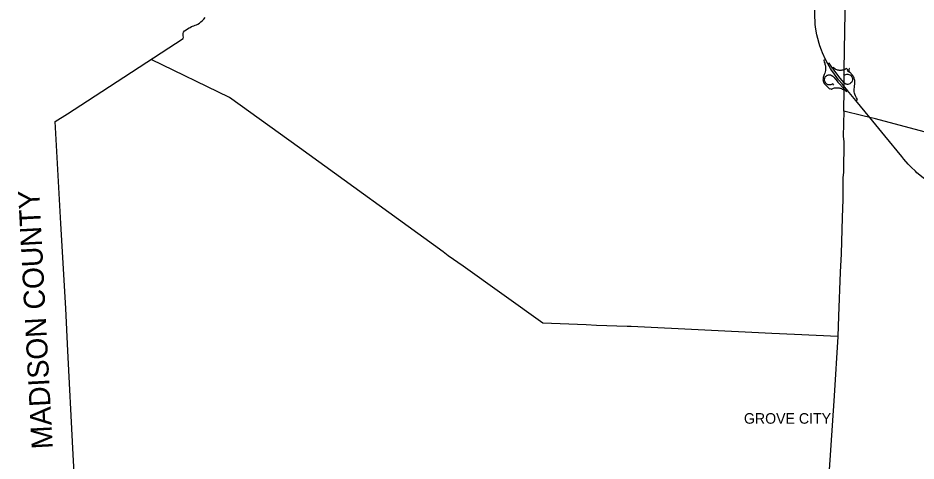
# Model space of a CAD drawing. Extents: x -1146 to -445, y -1283 to -822.
# Drawn here: x -1065.5 to -959.3, y -1137.5 to -1085.1 of the extents above; entities that cross this region are included whole.
import ezdxf

# ---------------------------------------------------------------- set-up
doc = ezdxf.new("R2010")
doc.units = 0
for name, color, linetype in [('GM_X_Adjacent_County_Text', 7, 'Continuous'), ('GM_X_Corporation_Text', 7, 'Continuous'), ('GM_X_County', 7, 'Continuous'), ('GM_X_Interchange_Ramps', 7, 'Continuous'), ('GM_X_Interstate_Route', 7, 'Continuous'), ('GM_X_Township', 7, 'Continuous')]:
    doc.layers.add(name, color=color, linetype=linetype)

msp = doc.modelspace()

# ---------------------------------------------------------------- linework, layer by layer
at = {"layer": 'GM_X_County'}
msp.add_lwpolyline([(-1058.38, -1148.55), (-1059.06, -1135.99), (-1059.63, -1124.47), (-1059.88, -1119.47), (-1060.45, -1109.43), (-1060.49, -1108.72), (-1061.15, -1097.4), (-1059.68, -1096.48), (-1057.3, -1094.93), (-1046.02, -1087.58), (-1045.98, -1087.41), (-1046.01, -1087.26), (-1046.02, -1087.13), (-1046, -1087), (-1045.95, -1086.84), (-1045.83, -1086.67), (-1045.65, -1086.55), (-1045.48, -1086.44), (-1045.31, -1086.33), (-1045.18, -1086.26), (-1045.01, -1086.17), (-1044.88, -1086.1), (-1044.74, -1086.06), (-1044.57, -1086.01), (-1044.44, -1085.96), (-1044.25, -1085.88), (-1044.08, -1085.77), (-1043.9, -1085.62), (-1043.73, -1085.45), (-1043.56, -1085.28), (-1043.4, -1085.09)], dxfattribs=at)
at = {"layer": 'GM_X_Interchange_Ramps'}
for points in [[(-970.05, -1090.04), (-970.26, -1090.15), (-970.19, -1090.37), (-970.14, -1090.48), (-970.11, -1090.61), (-970.08, -1090.71), (-970.06, -1090.81), (-970.05, -1090.91), (-970.04, -1091.04), (-970.05, -1091.17), (-970.05, -1091.26), (-970.06, -1091.37), (-970.1, -1091.53), (-970.13, -1091.66), (-970.19, -1091.84), (-970.3, -1092.18), (-970.32, -1092.27), (-970.33, -1092.35), (-970.34, -1092.43), (-970.33, -1092.53), (-970.32, -1092.63), (-970.29, -1092.71), (-970.23, -1092.83), (-970.15, -1092.95), (-969.67, -1093.41), (-969.52, -1093.56)], [(-967.9, -1091.8), (-967.82, -1091.89), (-967.65, -1091.83), (-967.53, -1091.79), (-967.4, -1091.79), (-967.28, -1091.81), (-967.17, -1091.85), (-967.07, -1091.92), (-966.99, -1091.99), (-966.92, -1092.09), (-966.88, -1092.19), (-966.85, -1092.31), (-966.85, -1092.45), (-966.88, -1092.6), (-966.92, -1092.69), (-966.98, -1092.77), (-967.07, -1092.86), (-967.18, -1092.93), (-967.3, -1092.97), (-967.39, -1092.99), (-967.48, -1092.99), (-967.56, -1092.98), (-967.62, -1092.96), (-967.74, -1092.9), (-967.83, -1092.83), (-968.32, -1092.26), (-968.71, -1091.74), (-969.14, -1091.16), (-969.22, -1091.06), (-969.6, -1090.48), (-969.76, -1090.58)], [(-967.4, -1091.27), (-967.58, -1091.12), (-967.58, -1091.12), (-967.66, -1091.18), (-967.75, -1091.22), (-967.82, -1091.25), (-967.91, -1091.29), (-968, -1091.31), (-968.11, -1091.33), (-968.21, -1091.34), (-968.29, -1091.35), (-968.41, -1091.34), (-968.51, -1091.32), (-968.62, -1091.3), (-968.72, -1091.27), (-968.82, -1091.22), (-968.9, -1091.18), (-969.15, -1091.01), (-969.22, -1091.06)], [(-967.17, -1091.57), (-967.21, -1091.61), (-967.44, -1091.4), (-967.48, -1091.36)], [(-966.44, -1094.92), (-966.27, -1094.77), (-966.38, -1094.59), (-966.5, -1094.33), (-966.57, -1094.16), (-966.61, -1094.02), (-966.64, -1093.86), (-966.65, -1093.7), (-966.65, -1093.52), (-966.63, -1093.38), (-966.61, -1093.2), (-966.58, -1092.94), (-966.56, -1092.79), (-966.56, -1092.66), (-966.57, -1092.53), (-966.6, -1092.4), (-966.64, -1092.28), (-966.69, -1092.16), (-966.76, -1092.06), (-966.83, -1091.96), (-966.87, -1091.9), (-967.17, -1091.57), (-967.23, -1091.46), (-967.25, -1091.37), (-967.25, -1091.27), (-967.23, -1091.19), (-967.19, -1091.12), (-967.24, -1091.08)], [(-969.06, -1093.07), (-969.19, -1092.95), (-969.34, -1093.02), (-969.43, -1093.04), (-969.54, -1093.05), (-969.64, -1093.06), (-969.75, -1093.04), (-969.82, -1093.01), (-969.9, -1092.96), (-969.99, -1092.84), (-970.05, -1092.78), (-970.09, -1092.7), (-970.13, -1092.62), (-970.15, -1092.53), (-970.15, -1092.45), (-970.15, -1092.37), (-970.13, -1092.28), (-970.11, -1092.21), (-970.07, -1092.14), (-970.03, -1092.08), (-969.98, -1092.03), (-969.92, -1091.97), (-969.85, -1091.92), (-969.77, -1091.89), (-969.69, -1091.87), (-969.6, -1091.85), (-969.52, -1091.86), (-969.44, -1091.87), (-969.38, -1091.89), (-969.19, -1092.02), (-969.05, -1092.15), (-968.66, -1092.63), (-968.58, -1092.72), (-967.84, -1093.53), (-967.8, -1093.58), (-967.59, -1093.83), (-967.45, -1093.7)], [(-969.45, -1093.47), (-969.35, -1093.58), (-969.18, -1093.49), (-969.08, -1093.46), (-968.98, -1093.42), (-968.86, -1093.4), (-968.77, -1093.39), (-968.67, -1093.39), (-968.55, -1093.39), (-968.43, -1093.41), (-968.33, -1093.44), (-968.25, -1093.46), (-968.15, -1093.5), (-968.06, -1093.55), (-968.01, -1093.58), (-967.89, -1093.66), (-967.84, -1093.62), (-967.8, -1093.58)]]:
    msp.add_lwpolyline(points, dxfattribs=at)
at = {"layer": 'GM_X_Interstate_Route'}
for points in [[(-971.29, -1085.15), (-971.32, -1084.27), (-971.31, -1084.02), (-971.28, -1083.55), (-971.24, -1083.09), (-971.2, -1082.81), (-971.11, -1082.38), (-970.77, -1080.75), (-970.3, -1078.68)], [(-971.18, -1086.46), (-971.25, -1085.93), (-971.28, -1085.42), (-971.29, -1085.15)], [(-970.89, -1087.86), (-970.96, -1087.59), (-971.06, -1087.14), (-971.18, -1086.46)], [(-969.32, -1091.3), (-969.44, -1091.13), (-969.61, -1090.84), (-969.76, -1090.58), (-970.05, -1090.04), (-970.4, -1089.28), (-970.52, -1088.96), (-970.72, -1088.42), (-970.88, -1087.89), (-970.89, -1087.86)], [(-968.5, -1092.45), (-969.19, -1091.5), (-969.32, -1091.3)], [(-967.54, -1093.59), (-967.84, -1093.23), (-968.06, -1092.95), (-968.5, -1092.45)], [(-967.45, -1093.7), (-967.54, -1093.59)], [(-961.03, -1101.52), (-963.02, -1099.09), (-964.82, -1096.9), (-966.44, -1094.92), (-967.45, -1093.7)], [(-959.41, -1103.25), (-959.91, -1102.77), (-960.25, -1102.42), (-960.78, -1101.83), (-961.03, -1101.52)], [(-956.56, -1105.31), (-957.01, -1105.08), (-957.77, -1104.58), (-958.5, -1104.04), (-959.23, -1103.43), (-959.41, -1103.25)]]:
    msp.add_lwpolyline(points, dxfattribs=at)
at = {"layer": 'GM_X_Township'}
for points in [[(-958.37, -1098.6), (-964.12, -1097.07), (-964.82, -1096.9), (-965.62, -1096.72), (-967.88, -1096.16), (-967.84, -1093.62), (-967.84, -1093.53), (-967.84, -1093.23), (-967.83, -1092.83), (-967.82, -1091.89), (-967.82, -1091.73), (-967.82, -1091.25), (-967.77, -1086.72), (-967.61, -1077.95)], [(-968.59, -1122.81), (-973.69, -1122.55), (-976.4, -1122.43), (-993.03, -1121.61), (-993.48, -1121.6), (-997.14, -1121.48), (-998.34, -1121.42), (-1003.48, -1121.2), (-1012.9, -1114.48), (-1014.67, -1113.27), (-1015.24, -1112.79), (-1032.25, -1100.51), (-1040.52, -1094.54), (-1049.8, -1090.04)], [(-967.88, -1096.16), (-967.96, -1099.15), (-967.87, -1099.73), (-967.93, -1103.33), (-967.97, -1103.75), (-967.99, -1103.98), (-968, -1104.43), (-968, -1106.62), (-968.07, -1108.72), (-968.18, -1113.02), (-968.3, -1115.19), (-968.49, -1120.39), (-968.59, -1122.81), (-969.02, -1129.82), (-969.63, -1139.16)]]:
    msp.add_lwpolyline(points, dxfattribs=at)

# ---------------------------------------------------------------- texts
at = {"layer": 'GM_X_Adjacent_County_Text'}
msp.add_text('MADISON COUNTY', height=2.5, rotation=93.0522, dxfattribs=at).set_placement((-1061.41, -1136.04))
at = {"layer": 'GM_X_Corporation_Text'}
msp.add_text('GROVE CITY', height=1.25, rotation=0, dxfattribs=at).set_placement((-979.69, -1133.1))

doc.saveas('drawing.dxf')
